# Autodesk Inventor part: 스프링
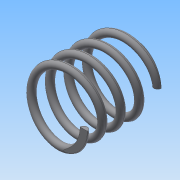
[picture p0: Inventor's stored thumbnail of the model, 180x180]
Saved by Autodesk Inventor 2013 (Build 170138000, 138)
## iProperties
Created: 2017-07
Part Number: 스프링
Material: 일반
Document SubType Name: Modeling
Designer: Administrator
Density: 1 g/cm^3
Mass: 0.658108 g
Surface Area: 13.3836 cm^2
Volume: 0.658108 cm^3
Author: Administrator
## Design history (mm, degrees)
sketch "스케치1"
  geometry: L1 (8.5, 0)-(0, 0); L2 (0, 0)-(0, 20.5); L3 (0, 20.5)-(8.5, 20.5); C1 r 1 at (8.5, 0); 1 further point
  constraints: 6 end point, 2 coincident, 1 centre point, 1 horizontal, 1 parallel, 1 perpendicular
  dimensions: "d0" = 8.5 distance of L1.start L1.end; "d2" = 20.5 distance of L1.end L2.end (derived); "d3" = 8.5 distance of L2.end L3.end; "d4" = 2 diameter of C1
feature "코일1" sketch "스케치1" pitch "d5" = 10; turns "d7" = 4; dims "d6" = 20.5 (= d2), "d8" = 0, angle "d9" = 90 deg, angle "d10" = 90 deg, "d11" = 0, "d12" = 0
sketch "스케치2"
  geometry: L1 (0, 11.573)-(20.5, 11.573); L2 (20.5, 11.573)-(20.5, -15.349); L3 (20.5, -15.349)-(0, -15.349); L4 (0, -15.349)-(0, 11.573); 1 further point
  constraints: 8 end point, 2 parallel, 1 horizontal, 1 perpendicular, 1 point on line
  dimensions: "d13" = 20.5 distance of L1.start L1.end (derived)
extrude "돌출2" sketch "스케치2" stored distance "d17" = 40; taper "d18" = 0 deg
node "솔리드1"
